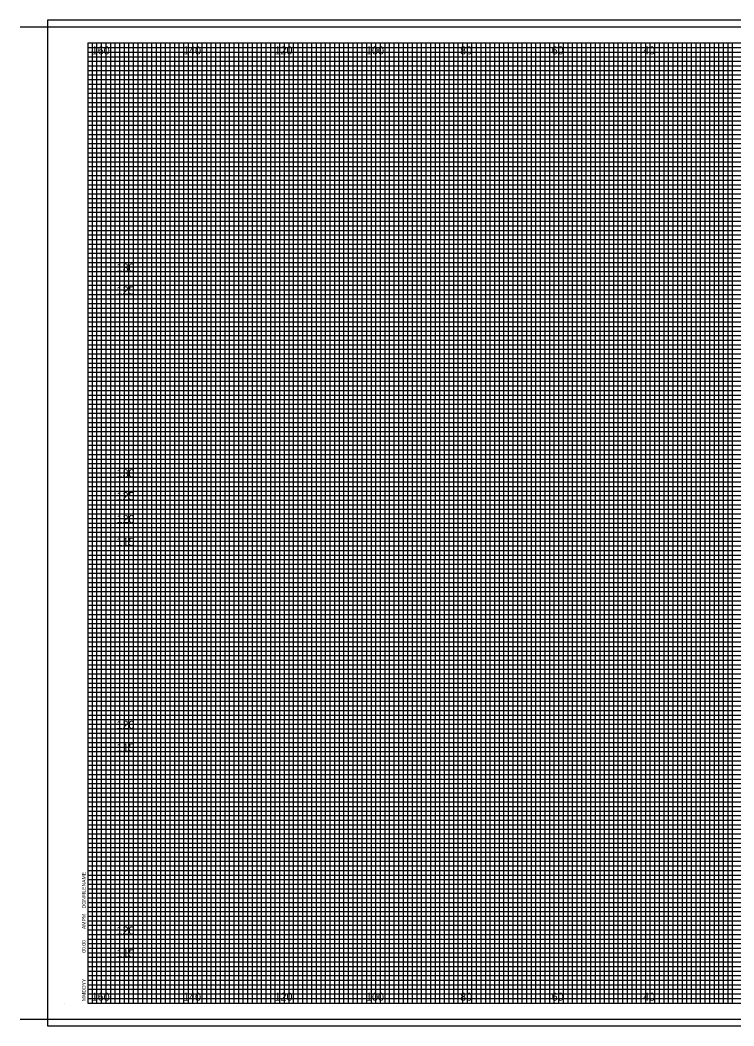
# Model space of a CAD drawing. Extents: x -3604 to 2303, y -13 to 9543.
# Drawn here: x -3604.5 to -3448.4, y 6224.1 to 6444.1 of the extents above; entities that cross this region are included whole.
import ezdxf

# ---------------------------------------------------------------- set-up
doc = ezdxf.new("R2010")
doc.units = 0
for name, color, linetype in [('SHEET_BORDER', 7, 'Continuous'), ('SHEET_DATE_DGN_TX', 7, 'Continuous'), ('SHEET_PLOTTING_SHAPE', 7, 'Continuous'), ('XS_SHEET_LABELS_ELEVATION', 7, 'Continuous'), ('XS_SHEET_LABELS_OFFSET', 7, 'Continuous'), ('XS_SHEET_MAJOR_GRIDS', 7, 'Continuous'), ('XS_SHEET_MEDIUM_GRIDS', 7, 'Continuous'), ('XS_SHEET_MINOR_GRIDS', 7, 'Continuous')]:
    doc.layers.add(name, color=color, linetype=linetype)

msp = doc.modelspace()

# ---------------------------------------------------------------- linework, layer by layer
at = {"layer": 'SHEET_BORDER'}
for p, q in [((-3604.48, 6442.59), (-3252.48, 6442.59)), ((-3589.68, 6439.09), (-3254.68, 6439.09)), ((-3589.68, 6439.09), (-3589.68, 6229.09)), ((-3594.68, 6229.09), (-3594.68, 6229.09)), ((-3589.68, 6229.09), (-3254.68, 6229.09)), ((-3604.48, 6225.59), (-3252.48, 6225.59))]:
    msp.add_line(p, q, dxfattribs=at)
at = {"layer": 'SHEET_PLOTTING_SHAPE'}
msp.add_lwpolyline([(-3598.48, 6224.09), (-3252.48, 6224.09), (-3252.48, 6444.09), (-3598.48, 6444.09)], close=True, dxfattribs=at)
at = {"layer": 'XS_SHEET_MAJOR_GRIDS'}
for p, q in [((-3584.68, 6229.09), (-3584.68, 6439.09)), ((-3574.68, 6229.09), (-3574.68, 6439.09)), ((-3564.68, 6229.09), (-3564.68, 6439.09)), ((-3554.68, 6229.09), (-3554.68, 6439.09)), ((-3544.68, 6229.09), (-3544.68, 6439.09)), ((-3534.68, 6229.09), (-3534.68, 6439.09)), ((-3524.68, 6229.09), (-3524.68, 6439.09)), ((-3514.68, 6229.09), (-3514.68, 6439.09)), ((-3504.68, 6229.09), (-3504.68, 6439.09)), ((-3494.68, 6229.09), (-3494.68, 6439.09)), ((-3484.68, 6229.09), (-3484.68, 6439.09)), ((-3474.68, 6229.09), (-3474.68, 6439.09)), ((-3464.68, 6229.09), (-3464.68, 6439.09)), ((-3454.68, 6229.09), (-3454.68, 6439.09)), ((-3589.68, 6429.09), (-3254.68, 6429.09)), ((-3589.68, 6419.09), (-3254.68, 6419.09)), ((-3589.68, 6409.09), (-3254.68, 6409.09)), ((-3589.68, 6399.09), (-3254.68, 6399.09)), ((-3589.68, 6389.09), (-3254.68, 6389.09)), ((-3589.68, 6379.09), (-3254.68, 6379.09)), ((-3589.68, 6369.09), (-3254.68, 6369.09)), ((-3589.68, 6359.09), (-3254.68, 6359.09)), ((-3589.68, 6349.09), (-3254.68, 6349.09)), ((-3589.68, 6339.09), (-3254.68, 6339.09)), ((-3589.68, 6329.09), (-3254.68, 6329.09)), ((-3589.68, 6319.09), (-3254.68, 6319.09)), ((-3589.68, 6309.09), (-3254.68, 6309.09)), ((-3589.68, 6299.09), (-3254.68, 6299.09)), ((-3589.68, 6289.09), (-3254.68, 6289.09)), ((-3589.68, 6279.09), (-3254.68, 6279.09)), ((-3589.68, 6269.09), (-3254.68, 6269.09)), ((-3589.68, 6259.09), (-3254.68, 6259.09)), ((-3589.68, 6249.09), (-3254.68, 6249.09)), ((-3589.68, 6239.09), (-3254.68, 6239.09))]:
    msp.add_line(p, q, dxfattribs=at)
at = {"layer": 'XS_SHEET_MEDIUM_GRIDS'}
for p, q in [((-3579.68, 6229.09), (-3579.68, 6439.09)), ((-3569.68, 6229.09), (-3569.68, 6439.09)), ((-3559.68, 6229.09), (-3559.68, 6439.09)), ((-3549.68, 6229.09), (-3549.68, 6439.09)), ((-3539.68, 6229.09), (-3539.68, 6439.09)), ((-3529.68, 6229.09), (-3529.68, 6439.09)), ((-3519.68, 6229.09), (-3519.68, 6439.09)), ((-3509.68, 6229.09), (-3509.68, 6439.09)), ((-3499.68, 6229.09), (-3499.68, 6439.09)), ((-3489.68, 6229.09), (-3489.68, 6439.09)), ((-3479.68, 6229.09), (-3479.68, 6439.09)), ((-3469.68, 6229.09), (-3469.68, 6439.09)), ((-3459.68, 6229.09), (-3459.68, 6439.09)), ((-3449.68, 6229.09), (-3449.68, 6439.09)), ((-3589.68, 6434.09), (-3281.68, 6434.09)), ((-3589.68, 6424.09), (-3254.68, 6424.09)), ((-3589.68, 6414.09), (-3254.68, 6414.09)), ((-3589.68, 6404.09), (-3254.68, 6404.09)), ((-3589.68, 6394.09), (-3254.68, 6394.09)), ((-3589.68, 6384.09), (-3254.68, 6384.09)), ((-3589.68, 6374.09), (-3254.68, 6374.09)), ((-3589.68, 6364.09), (-3254.68, 6364.09)), ((-3589.68, 6354.09), (-3254.68, 6354.09)), ((-3589.68, 6344.09), (-3254.68, 6344.09)), ((-3589.68, 6334.09), (-3254.68, 6334.09)), ((-3589.68, 6324.09), (-3254.68, 6324.09)), ((-3589.68, 6314.09), (-3254.68, 6314.09)), ((-3589.68, 6304.09), (-3254.68, 6304.09)), ((-3589.68, 6294.09), (-3254.68, 6294.09)), ((-3589.68, 6284.09), (-3254.68, 6284.09)), ((-3589.68, 6274.09), (-3254.68, 6274.09)), ((-3589.68, 6264.09), (-3254.68, 6264.09)), ((-3589.68, 6254.09), (-3254.68, 6254.09)), ((-3589.68, 6244.09), (-3254.68, 6244.09)), ((-3589.68, 6234.09), (-3264.68, 6234.09))]:
    msp.add_line(p, q, dxfattribs=at)
at = {"layer": 'XS_SHEET_MINOR_GRIDS'}
for p, q in [((-3589.68, 6438.09), (-3281.68, 6438.09)), ((-3588.68, 6229.09), (-3588.68, 6439.09)), ((-3587.68, 6229.09), (-3587.68, 6439.09)), ((-3586.68, 6229.09), (-3586.68, 6439.09)), ((-3585.68, 6229.09), (-3585.68, 6439.09)), ((-3583.68, 6229.09), (-3583.68, 6439.09)), ((-3582.68, 6229.09), (-3582.68, 6439.09)), ((-3581.68, 6229.09), (-3581.68, 6439.09)), ((-3580.68, 6229.09), (-3580.68, 6439.09)), ((-3578.68, 6229.09), (-3578.68, 6439.09)), ((-3577.68, 6229.09), (-3577.68, 6439.09)), ((-3576.68, 6229.09), (-3576.68, 6439.09)), ((-3575.68, 6229.09), (-3575.68, 6439.09)), ((-3573.68, 6229.09), (-3573.68, 6439.09)), ((-3572.68, 6229.09), (-3572.68, 6439.09)), ((-3571.68, 6229.09), (-3571.68, 6439.09)), ((-3570.68, 6229.09), (-3570.68, 6439.09)), ((-3568.68, 6229.09), (-3568.68, 6439.09)), ((-3567.68, 6229.09), (-3567.68, 6439.09)), ((-3566.68, 6229.09), (-3566.68, 6439.09)), ((-3565.68, 6229.09), (-3565.68, 6439.09)), ((-3563.68, 6229.09), (-3563.68, 6439.09)), ((-3562.68, 6229.09), (-3562.68, 6439.09)), ((-3561.68, 6229.09), (-3561.68, 6439.09)), ((-3560.68, 6229.09), (-3560.68, 6439.09)), ((-3558.68, 6229.09), (-3558.68, 6439.09)), ((-3557.68, 6229.09), (-3557.68, 6439.09)), ((-3556.68, 6229.09), (-3556.68, 6439.09)), ((-3555.68, 6229.09), (-3555.68, 6439.09)), ((-3553.68, 6229.09), (-3553.68, 6439.09)), ((-3552.68, 6229.09), (-3552.68, 6439.09)), ((-3551.68, 6229.09), (-3551.68, 6439.09)), ((-3550.68, 6229.09), (-3550.68, 6439.09)), ((-3548.68, 6229.09), (-3548.68, 6439.09)), ((-3547.68, 6229.09), (-3547.68, 6439.09)), ((-3546.68, 6229.09), (-3546.68, 6439.09)), ((-3545.68, 6229.09), (-3545.68, 6439.09)), ((-3543.68, 6229.09), (-3543.68, 6439.09)), ((-3542.68, 6229.09), (-3542.68, 6439.09)), ((-3541.68, 6229.09), (-3541.68, 6439.09)), ((-3540.68, 6229.09), (-3540.68, 6439.09)), ((-3538.68, 6229.09), (-3538.68, 6439.09)), ((-3537.68, 6229.09), (-3537.68, 6439.09)), ((-3536.68, 6229.09), (-3536.68, 6439.09)), ((-3535.68, 6229.09), (-3535.68, 6439.09)), ((-3533.68, 6229.09), (-3533.68, 6439.09)), ((-3532.68, 6229.09), (-3532.68, 6439.09)), ((-3531.68, 6229.09), (-3531.68, 6439.09)), ((-3530.68, 6229.09), (-3530.68, 6439.09)), ((-3528.68, 6229.09), (-3528.68, 6439.09)), ((-3527.68, 6229.09), (-3527.68, 6439.09)), ((-3526.68, 6229.09), (-3526.68, 6439.09)), ((-3525.68, 6229.09), (-3525.68, 6439.09)), ((-3523.68, 6229.09), (-3523.68, 6439.09)), ((-3522.68, 6229.09), (-3522.68, 6439.09)), ((-3521.68, 6229.09), (-3521.68, 6439.09)), ((-3520.68, 6229.09), (-3520.68, 6439.09)), ((-3518.68, 6229.09), (-3518.68, 6439.09)), ((-3517.68, 6229.09), (-3517.68, 6439.09)), ((-3516.68, 6229.09), (-3516.68, 6439.09)), ((-3515.68, 6229.09), (-3515.68, 6439.09)), ((-3513.68, 6229.09), (-3513.68, 6439.09)), ((-3512.68, 6229.09), (-3512.68, 6439.09)), ((-3511.68, 6229.09), (-3511.68, 6439.09)), ((-3510.68, 6229.09), (-3510.68, 6439.09)), ((-3508.68, 6229.09), (-3508.68, 6439.09)), ((-3507.68, 6229.09), (-3507.68, 6439.09)), ((-3506.68, 6229.09), (-3506.68, 6439.09)), ((-3505.68, 6229.09), (-3505.68, 6439.09)), ((-3503.68, 6229.09), (-3503.68, 6439.09)), ((-3502.68, 6229.09), (-3502.68, 6439.09)), ((-3501.68, 6229.09), (-3501.68, 6439.09)), ((-3500.68, 6229.09), (-3500.68, 6439.09)), ((-3498.68, 6229.09), (-3498.68, 6439.09)), ((-3497.68, 6229.09), (-3497.68, 6439.09)), ((-3496.68, 6229.09), (-3496.68, 6439.09)), ((-3495.68, 6229.09), (-3495.68, 6439.09)), ((-3493.68, 6229.09), (-3493.68, 6439.09)), ((-3492.68, 6229.09), (-3492.68, 6439.09)), ((-3491.68, 6229.09), (-3491.68, 6439.09)), ((-3490.68, 6229.09), (-3490.68, 6439.09)), ((-3488.68, 6229.09), (-3488.68, 6439.09)), ((-3487.68, 6229.09), (-3487.68, 6439.09)), ((-3486.68, 6229.09), (-3486.68, 6439.09)), ((-3485.68, 6229.09), (-3485.68, 6439.09)), ((-3483.68, 6229.09), (-3483.68, 6439.09)), ((-3482.68, 6229.09), (-3482.68, 6439.09)), ((-3481.68, 6229.09), (-3481.68, 6439.09)), ((-3480.68, 6229.09), (-3480.68, 6439.09)), ((-3478.68, 6229.09), (-3478.68, 6439.09)), ((-3477.68, 6229.09), (-3477.68, 6439.09)), ((-3476.68, 6229.09), (-3476.68, 6439.09)), ((-3475.68, 6229.09), (-3475.68, 6439.09)), ((-3473.68, 6229.09), (-3473.68, 6439.09)), ((-3472.68, 6229.09), (-3472.68, 6439.09)), ((-3471.68, 6229.09), (-3471.68, 6439.09)), ((-3470.68, 6229.09), (-3470.68, 6439.09)), ((-3468.68, 6229.09), (-3468.68, 6439.09)), ((-3467.68, 6229.09), (-3467.68, 6439.09)), ((-3466.68, 6229.09), (-3466.68, 6439.09)), ((-3465.68, 6229.09), (-3465.68, 6439.09)), ((-3463.68, 6229.09), (-3463.68, 6439.09)), ((-3462.68, 6229.09), (-3462.68, 6439.09)), ((-3461.68, 6229.09), (-3461.68, 6439.09)), ((-3460.68, 6229.09), (-3460.68, 6439.09)), ((-3458.68, 6229.09), (-3458.68, 6439.09)), ((-3457.68, 6229.09), (-3457.68, 6439.09)), ((-3456.68, 6229.09), (-3456.68, 6439.09)), ((-3455.68, 6229.09), (-3455.68, 6439.09)), ((-3453.68, 6229.09), (-3453.68, 6439.09)), ((-3452.68, 6229.09), (-3452.68, 6439.09)), ((-3451.68, 6229.09), (-3451.68, 6439.09)), ((-3450.68, 6229.09), (-3450.68, 6439.09)), ((-3448.68, 6229.09), (-3448.68, 6439.09)), ((-3589.68, 6437.09), (-3281.68, 6437.09)), ((-3589.68, 6436.09), (-3281.68, 6436.09)), ((-3589.68, 6435.09), (-3281.68, 6435.09)), ((-3589.68, 6433.09), (-3281.68, 6433.09)), ((-3589.68, 6432.09), (-3281.68, 6432.09)), ((-3589.68, 6431.09), (-3281.68, 6431.09)), ((-3589.68, 6430.09), (-3254.68, 6430.09)), ((-3589.68, 6428.09), (-3254.68, 6428.09)), ((-3589.68, 6427.09), (-3254.68, 6427.09)), ((-3589.68, 6426.09), (-3254.68, 6426.09)), ((-3589.68, 6425.09), (-3254.68, 6425.09)), ((-3589.68, 6423.09), (-3254.68, 6423.09)), ((-3589.68, 6422.09), (-3254.68, 6422.09)), ((-3589.68, 6421.09), (-3254.68, 6421.09)), ((-3589.68, 6420.09), (-3254.68, 6420.09)), ((-3589.68, 6418.09), (-3254.68, 6418.09)), ((-3589.68, 6417.09), (-3254.68, 6417.09)), ((-3589.68, 6416.09), (-3254.68, 6416.09)), ((-3589.68, 6415.09), (-3254.68, 6415.09)), ((-3589.68, 6413.09), (-3254.68, 6413.09)), ((-3589.68, 6412.09), (-3254.68, 6412.09)), ((-3589.68, 6411.09), (-3254.68, 6411.09)), ((-3589.68, 6410.09), (-3254.68, 6410.09)), ((-3589.68, 6408.09), (-3254.68, 6408.09)), ((-3589.68, 6407.09), (-3254.68, 6407.09)), ((-3589.68, 6406.09), (-3254.68, 6406.09)), ((-3589.68, 6405.09), (-3254.68, 6405.09)), ((-3589.68, 6403.09), (-3254.68, 6403.09)), ((-3589.68, 6402.09), (-3254.68, 6402.09)), ((-3589.68, 6401.09), (-3254.68, 6401.09)), ((-3589.68, 6400.09), (-3254.68, 6400.09)), ((-3589.68, 6398.09), (-3254.68, 6398.09)), ((-3589.68, 6397.09), (-3254.68, 6397.09)), ((-3589.68, 6396.09), (-3254.68, 6396.09)), ((-3589.68, 6395.09), (-3254.68, 6395.09)), ((-3589.68, 6393.09), (-3254.68, 6393.09)), ((-3589.68, 6392.09), (-3254.68, 6392.09)), ((-3589.68, 6391.09), (-3254.68, 6391.09)), ((-3589.68, 6390.09), (-3254.68, 6390.09)), ((-3589.68, 6388.09), (-3254.68, 6388.09)), ((-3589.68, 6387.09), (-3254.68, 6387.09)), ((-3589.68, 6386.09), (-3254.68, 6386.09)), ((-3589.68, 6385.09), (-3254.68, 6385.09)), ((-3589.68, 6383.09), (-3254.68, 6383.09)), ((-3589.68, 6382.09), (-3254.68, 6382.09)), ((-3589.68, 6381.09), (-3254.68, 6381.09)), ((-3589.68, 6380.09), (-3254.68, 6380.09)), ((-3589.68, 6378.09), (-3254.68, 6378.09)), ((-3589.68, 6377.09), (-3254.68, 6377.09)), ((-3589.68, 6376.09), (-3254.68, 6376.09)), ((-3589.68, 6375.09), (-3254.68, 6375.09)), ((-3589.68, 6373.09), (-3254.68, 6373.09)), ((-3589.68, 6372.09), (-3254.68, 6372.09)), ((-3589.68, 6371.09), (-3254.68, 6371.09)), ((-3589.68, 6370.09), (-3254.68, 6370.09)), ((-3589.68, 6368.09), (-3254.68, 6368.09)), ((-3589.68, 6367.09), (-3254.68, 6367.09)), ((-3589.68, 6366.09), (-3254.68, 6366.09)), ((-3589.68, 6365.09), (-3254.68, 6365.09)), ((-3589.68, 6363.09), (-3254.68, 6363.09)), ((-3589.68, 6362.09), (-3254.68, 6362.09)), ((-3589.68, 6361.09), (-3254.68, 6361.09)), ((-3589.68, 6360.09), (-3254.68, 6360.09)), ((-3589.68, 6358.09), (-3254.68, 6358.09)), ((-3589.68, 6357.09), (-3254.68, 6357.09)), ((-3589.68, 6356.09), (-3254.68, 6356.09)), ((-3589.68, 6355.09), (-3254.68, 6355.09)), ((-3589.68, 6353.09), (-3254.68, 6353.09)), ((-3589.68, 6352.09), (-3254.68, 6352.09)), ((-3589.68, 6351.09), (-3254.68, 6351.09)), ((-3589.68, 6350.09), (-3254.68, 6350.09)), ((-3589.68, 6348.09), (-3254.68, 6348.09)), ((-3589.68, 6347.09), (-3254.68, 6347.09)), ((-3589.68, 6346.09), (-3254.68, 6346.09)), ((-3589.68, 6345.09), (-3254.68, 6345.09)), ((-3589.68, 6343.09), (-3254.68, 6343.09)), ((-3589.68, 6342.09), (-3254.68, 6342.09)), ((-3589.68, 6341.09), (-3254.68, 6341.09)), ((-3589.68, 6340.09), (-3254.68, 6340.09)), ((-3589.68, 6338.09), (-3254.68, 6338.09)), ((-3589.68, 6337.09), (-3254.68, 6337.09)), ((-3589.68, 6336.09), (-3254.68, 6336.09)), ((-3589.68, 6335.09), (-3254.68, 6335.09)), ((-3589.68, 6333.09), (-3254.68, 6333.09)), ((-3589.68, 6332.09), (-3254.68, 6332.09)), ((-3589.68, 6331.09), (-3254.68, 6331.09)), ((-3589.68, 6330.09), (-3254.68, 6330.09)), ((-3589.68, 6328.09), (-3254.68, 6328.09)), ((-3589.68, 6327.09), (-3254.68, 6327.09)), ((-3589.68, 6326.09), (-3254.68, 6326.09)), ((-3589.68, 6325.09), (-3254.68, 6325.09)), ((-3589.68, 6323.09), (-3254.68, 6323.09)), ((-3589.68, 6322.09), (-3254.68, 6322.09)), ((-3589.68, 6321.09), (-3254.68, 6321.09)), ((-3589.68, 6320.09), (-3254.68, 6320.09)), ((-3589.68, 6318.09), (-3254.68, 6318.09)), ((-3589.68, 6317.09), (-3254.68, 6317.09)), ((-3589.68, 6316.09), (-3254.68, 6316.09)), ((-3589.68, 6315.09), (-3254.68, 6315.09)), ((-3589.68, 6313.09), (-3254.68, 6313.09)), ((-3589.68, 6312.09), (-3254.68, 6312.09)), ((-3589.68, 6311.09), (-3254.68, 6311.09)), ((-3589.68, 6310.09), (-3254.68, 6310.09)), ((-3589.68, 6308.09), (-3254.68, 6308.09)), ((-3589.68, 6307.09), (-3254.68, 6307.09)), ((-3589.68, 6306.09), (-3254.68, 6306.09)), ((-3589.68, 6305.09), (-3254.68, 6305.09)), ((-3589.68, 6303.09), (-3254.68, 6303.09)), ((-3589.68, 6302.09), (-3254.68, 6302.09)), ((-3589.68, 6301.09), (-3254.68, 6301.09)), ((-3589.68, 6300.09), (-3254.68, 6300.09)), ((-3589.68, 6298.09), (-3254.68, 6298.09)), ((-3589.68, 6297.09), (-3254.68, 6297.09)), ((-3589.68, 6296.09), (-3254.68, 6296.09)), ((-3589.68, 6295.09), (-3254.68, 6295.09)), ((-3589.68, 6293.09), (-3254.68, 6293.09)), ((-3589.68, 6292.09), (-3254.68, 6292.09)), ((-3589.68, 6291.09), (-3254.68, 6291.09)), ((-3589.68, 6290.09), (-3254.68, 6290.09)), ((-3589.68, 6288.09), (-3254.68, 6288.09)), ((-3589.68, 6287.09), (-3254.68, 6287.09)), ((-3589.68, 6286.09), (-3254.68, 6286.09)), ((-3589.68, 6285.09), (-3254.68, 6285.09)), ((-3589.68, 6283.09), (-3254.68, 6283.09)), ((-3589.68, 6282.09), (-3254.68, 6282.09)), ((-3589.68, 6281.09), (-3254.68, 6281.09)), ((-3589.68, 6280.09), (-3254.68, 6280.09)), ((-3589.68, 6278.09), (-3254.68, 6278.09)), ((-3589.68, 6277.09), (-3254.68, 6277.09)), ((-3589.68, 6276.09), (-3254.68, 6276.09)), ((-3589.68, 6275.09), (-3254.68, 6275.09)), ((-3589.68, 6273.09), (-3254.68, 6273.09)), ((-3589.68, 6272.09), (-3254.68, 6272.09)), ((-3589.68, 6271.09), (-3254.68, 6271.09)), ((-3589.68, 6270.09), (-3254.68, 6270.09)), ((-3589.68, 6268.09), (-3254.68, 6268.09)), ((-3589.68, 6267.09), (-3254.68, 6267.09)), ((-3589.68, 6266.09), (-3254.68, 6266.09)), ((-3589.68, 6265.09), (-3254.68, 6265.09)), ((-3589.68, 6263.09), (-3254.68, 6263.09)), ((-3589.68, 6262.09), (-3254.68, 6262.09)), ((-3589.68, 6261.09), (-3254.68, 6261.09)), ((-3589.68, 6260.09), (-3254.68, 6260.09)), ((-3589.68, 6258.09), (-3254.68, 6258.09)), ((-3589.68, 6257.09), (-3254.68, 6257.09)), ((-3589.68, 6256.09), (-3254.68, 6256.09)), ((-3589.68, 6255.09), (-3254.68, 6255.09)), ((-3589.68, 6253.09), (-3254.68, 6253.09)), ((-3589.68, 6252.09), (-3254.68, 6252.09)), ((-3589.68, 6251.09), (-3254.68, 6251.09)), ((-3589.68, 6250.09), (-3254.68, 6250.09)), ((-3589.68, 6250.09), (-3254.68, 6250.09)), ((-3589.68, 6250.09), (-3254.68, 6250.09)), ((-3589.68, 6248.09), (-3254.68, 6248.09)), ((-3589.68, 6247.09), (-3254.68, 6247.09)), ((-3589.68, 6246.09), (-3254.68, 6246.09)), ((-3589.68, 6245.09), (-3254.68, 6245.09)), ((-3589.68, 6243.09), (-3254.68, 6243.09)), ((-3589.68, 6242.09), (-3254.68, 6242.09)), ((-3589.68, 6241.09), (-3254.68, 6241.09)), ((-3589.68, 6240.09), (-3254.68, 6240.09)), ((-3589.68, 6238.09), (-3264.68, 6238.09)), ((-3589.68, 6237.09), (-3264.68, 6237.09)), ((-3589.68, 6236.09), (-3264.68, 6236.09)), ((-3589.68, 6235.09), (-3264.68, 6235.09)), ((-3589.68, 6235.09), (-3264.68, 6235.09)), ((-3589.68, 6235.09), (-3264.68, 6235.09)), ((-3589.68, 6233.09), (-3264.68, 6233.09)), ((-3589.68, 6232.09), (-3264.68, 6232.09)), ((-3589.68, 6231.09), (-3264.68, 6231.09)), ((-3589.68, 6230.09), (-3264.68, 6230.09))]:
    msp.add_line(p, q, dxfattribs=at)

# ---------------------------------------------------------------- texts
at = {"layer": 'SHEET_DATE_DGN_TX'}
for s, p in [('DGNFILENAME', (-3590.15, 6249.79)), ('AMPM', (-3590.15, 6245.27)), ('00:00', (-3590.15, 6240.09)), ('MMDDYY', (-3590.15, 6229.51))]:
    msp.add_text(s, height=0.8, rotation=90, dxfattribs=at).set_placement(p)
at = {"layer": 'XS_SHEET_LABELS_ELEVATION'}
for s, p in [('  130  ', (-3584.68, 6389.09)), ('  125  ', (-3584.68, 6384.09)), ('  130  ', (-3584.68, 6344.09)), ('  125  ', (-3584.68, 6339.09)), ('  120  ', (-3584.68, 6334.09)), ('  115  ', (-3584.68, 6329.09)), ('  120  ', (-3584.68, 6289.09)), ('  115  ', (-3584.68, 6284.09)), ('  120  ', (-3584.68, 6244.09)), ('  115  ', (-3584.68, 6239.09))]:
    msp.add_text(s, height=1.75, dxfattribs=at).set_placement(p)
at = {"layer": 'XS_SHEET_LABELS_OFFSET'}
for s, p in [('  160  ', (-3590.11, 6436.59)), ('  140  ', (-3570.13, 6436.59)), ('  120  ', (-3550.13, 6436.59)), ('  100  ', (-3530.13, 6436.59)), ('  80  ', (-3509.56, 6436.59)), ('  60  ', (-3489.55, 6436.59)), ('  40  ', (-3469.56, 6436.59)), ('  160  ', (-3590.11, 6229.59)), ('  140  ', (-3570.13, 6229.59)), ('  120  ', (-3550.13, 6229.59)), ('  100  ', (-3530.13, 6229.59)), ('  80  ', (-3509.56, 6229.59)), ('  60  ', (-3489.55, 6229.59)), ('  40  ', (-3469.56, 6229.59))]:
    msp.add_text(s, height=1.75, dxfattribs=at).set_placement(p)

doc.saveas('drawing.dxf')
